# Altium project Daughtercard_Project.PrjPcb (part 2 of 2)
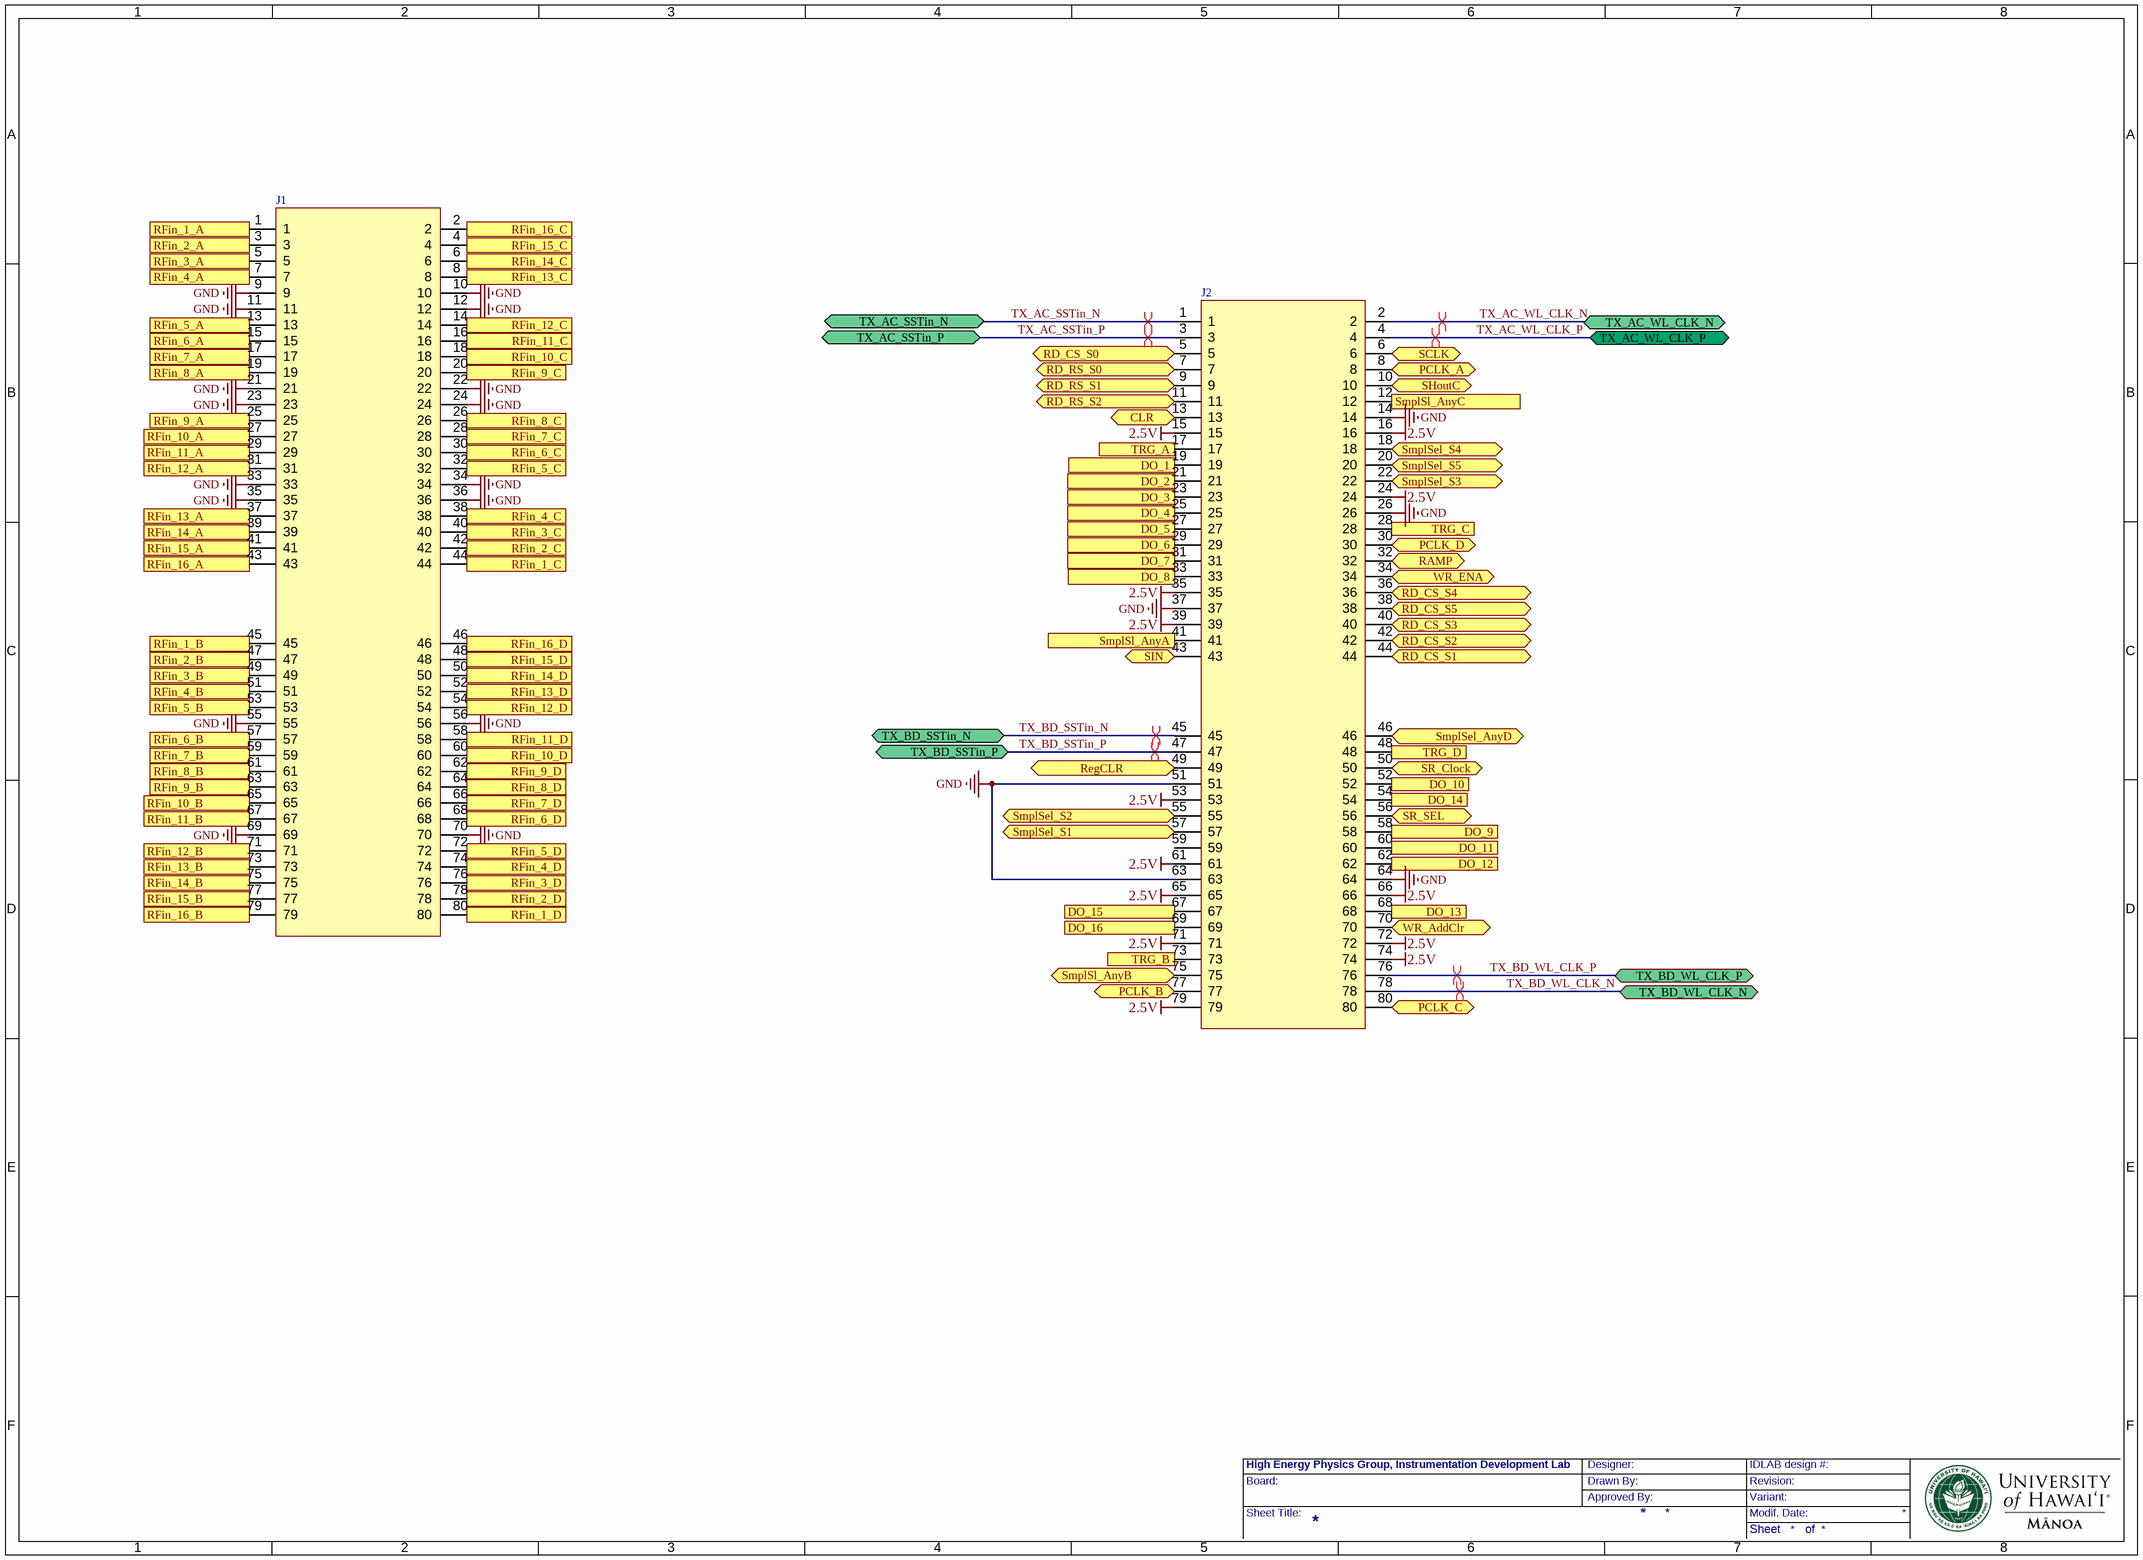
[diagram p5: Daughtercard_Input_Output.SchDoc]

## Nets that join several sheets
2.5V: TargetX_A (32 pins), TargetX_B (32 pins), TargetX_C (32 pins), TargetX_D (32 pins), Daughtercard_Input_Output (13 pins)
GND: TargetX_A (61 pins), TargetX_B (61 pins), TargetX_C (61 pins), TargetX_D (61 pins), Daughtercard_Input_Output (22 pins)
DO_1: TargetX_A (UA.91), TargetX_B (UB.91), TargetX_C (UC.91), TargetX_D (UD.91)
DO_2: TargetX_A (UA.90), TargetX_B (UB.90), TargetX_C (UC.90), TargetX_D (UD.90)
DO_3: TargetX_A (UA.89), TargetX_B (UB.89), TargetX_C (UC.89), TargetX_D (UD.89)
DO_4: TargetX_A (UA.88), TargetX_B (UB.88), TargetX_C (UC.88), TargetX_D (UD.88)
DO_5: TargetX_A (UA.87), TargetX_B (UB.87), TargetX_C (UC.87), TargetX_D (UD.87)
DO_6: TargetX_A (UA.86), TargetX_B (UB.86), TargetX_C (UC.86), TargetX_D (UD.86)
DO_7: TargetX_A (UA.85), TargetX_B (UB.85), TargetX_C (UC.85), TargetX_D (UD.85)
DO_8: TargetX_A (UA.84), TargetX_B (UB.84), TargetX_C (UC.84), TargetX_D (UD.84)
DO_9: TargetX_A (UA.76), TargetX_B (UB.76), TargetX_C (UC.76), TargetX_D (UD.76)
DO_10: TargetX_A (UA.75), TargetX_B (UB.75), TargetX_C (UC.75), TargetX_D (UD.75)
DO_11: TargetX_A (UA.74), TargetX_B (UB.74), TargetX_C (UC.74), TargetX_D (UD.74)
DO_12: TargetX_A (UA.73), TargetX_B (UB.73), TargetX_C (UC.73), TargetX_D (UD.73)
DO_13: TargetX_A (UA.72), TargetX_B (UB.72), TargetX_C (UC.72), TargetX_D (UD.72)
DO_14: TargetX_A (UA.71), TargetX_B (UB.71), TargetX_C (UC.71), TargetX_D (UD.71)
DO_15: TargetX_A (UA.70), TargetX_B (UB.70), TargetX_C (UC.70), TargetX_D (UD.70)
DO_16: TargetX_A (UA.69), TargetX_B (UB.69), TargetX_C (UC.69), TargetX_D (UD.69)
PCLK_A: TargetX_A (UA.37), Daughtercard_Input_Output (J2.8)
PCLK_B: TargetX_B (UB.37), Daughtercard_Input_Output (J2.77)
PCLK_C: TargetX_C (UC.37), Daughtercard_Input_Output (J2.80)
PCLK_D: TargetX_D (UD.37), Daughtercard_Input_Output (J2.30)
RD_CS_S0: TargetX_A (UA.46), TargetX_B (UB.46), TargetX_C (UC.46), TargetX_D (UD.46), Daughtercard_Input_Output (J2.5)
RD_CS_S1: TargetX_A (UA.47), TargetX_B (UB.47), TargetX_C (UC.47), TargetX_D (UD.47), Daughtercard_Input_Output (J2.44)
RD_CS_S2: TargetX_A (UA.48), TargetX_B (UB.48), TargetX_C (UC.48), TargetX_D (UD.48), Daughtercard_Input_Output (J2.42)
RD_CS_S3: TargetX_A (UA.49), TargetX_B (UB.49), TargetX_C (UC.49), TargetX_D (UD.49), Daughtercard_Input_Output (J2.40)
RD_CS_S4: TargetX_A (UA.50), TargetX_B (UB.50), TargetX_C (UC.50), TargetX_D (UD.50), Daughtercard_Input_Output (J2.36)
RD_CS_S5: TargetX_A (UA.51), TargetX_B (UB.51), TargetX_C (UC.51), TargetX_D (UD.51), Daughtercard_Input_Output (J2.38)
RD_RS_S0: TargetX_A (UA.105), TargetX_B (UB.105), TargetX_C (UC.105), TargetX_D (UD.105), Daughtercard_Input_Output (J2.7)
RD_RS_S1: TargetX_A (UA.104), TargetX_B (UB.104), TargetX_C (UC.104), TargetX_D (UD.104), Daughtercard_Input_Output (J2.9)
RD_RS_S2: TargetX_A (UA.103), TargetX_B (UB.103), TargetX_C (UC.103), TargetX_D (UD.103), Daughtercard_Input_Output (J2.11)
RegCLR: TargetX_A (UA.99), TargetX_B (UB.99), TargetX_C (UC.99), TargetX_D (UD.99), Daughtercard_Input_Output (J2.49)
RFin_1_A: TargetX_A (R1A.2 UA.1), Daughtercard_Input_Output (J1.1)
RFin_1_B: TargetX_B (R1B.2 UB.1), Daughtercard_Input_Output (J1.45)
RFin_1_C: TargetX_C (R1C.2 UC.1), Daughtercard_Input_Output (J1.44)
RFin_1_D: TargetX_D (R1D.2 UD.1), Daughtercard_Input_Output (J1.80)
RFin_2_A: TargetX_A (R2A.2 UA.3), Daughtercard_Input_Output (J1.3)
RFin_2_B: TargetX_B (R2B.2 UB.3), Daughtercard_Input_Output (J1.47)
RFin_2_C: TargetX_C (R2C.2 UC.3), Daughtercard_Input_Output (J1.42)
RFin_2_D: TargetX_D (R2D.2 UD.3), Daughtercard_Input_Output (J1.78)
RFin_3_A: TargetX_A (R3A.2 UA.5), Daughtercard_Input_Output (J1.5)
RFin_3_B: TargetX_B (R3B.2 UB.5), Daughtercard_Input_Output (J1.49)
RFin_3_C: TargetX_C (R3C.2 UC.5), Daughtercard_Input_Output (J1.40)
RFin_3_D: TargetX_D (R3D.2 UD.5), Daughtercard_Input_Output (J1.76)
RFin_4_A: TargetX_A (R4A.2 UA.7), Daughtercard_Input_Output (J1.7)
RFin_4_B: TargetX_B (R4B.2 UB.7), Daughtercard_Input_Output (J1.51)
RFin_4_C: TargetX_C (R4C.2 UC.7), Daughtercard_Input_Output (J1.38)
RFin_4_D: TargetX_D (R4D.2 UD.7), Daughtercard_Input_Output (J1.74)
RFin_5_A: TargetX_A (R5A.2 UA.9), Daughtercard_Input_Output (J1.13)
RFin_5_B: TargetX_B (R5B.2 UB.9), Daughtercard_Input_Output (J1.53)
RFin_5_C: TargetX_C (R5C.2 UC.9), Daughtercard_Input_Output (J1.32)
RFin_5_D: TargetX_D (R5D.2 UD.9), Daughtercard_Input_Output (J1.72)
RFin_6_A: TargetX_A (R6A.2 UA.11), Daughtercard_Input_Output (J1.15)
RFin_6_B: TargetX_B (R6B.2 UB.11), Daughtercard_Input_Output (J1.57)
RFin_6_C: TargetX_C (R6C.2 UC.11), Daughtercard_Input_Output (J1.30)
RFin_6_D: TargetX_D (R6D.2 UD.11), Daughtercard_Input_Output (J1.68)
RFin_7_A: TargetX_A (R7A.2 UA.13), Daughtercard_Input_Output (J1.17)
RFin_7_B: TargetX_B (R7B.2 UB.13), Daughtercard_Input_Output (J1.59)
RFin_7_C: TargetX_C (R7C.2 UC.13), Daughtercard_Input_Output (J1.28)
RFin_7_D: TargetX_D (R7D.2 UD.13), Daughtercard_Input_Output (J1.66)
RFin_8_A: TargetX_A (R8A.2 UA.15), Daughtercard_Input_Output (J1.19)
RFin_8_B: TargetX_B (R8B.2 UB.15), Daughtercard_Input_Output (J1.61)
RFin_8_C: TargetX_C (R8C.2 UC.15), Daughtercard_Input_Output (J1.26)
RFin_8_D: TargetX_D (R8D.2 UD.15), Daughtercard_Input_Output (J1.64)
RFin_9_A: TargetX_A (R9A.2 UA.17), Daughtercard_Input_Output (J1.25)
RFin_9_B: TargetX_B (R9B.2 UB.17), Daughtercard_Input_Output (J1.63)
RFin_9_C: TargetX_C (R9C.2 UC.17), Daughtercard_Input_Output (J1.20)
RFin_9_D: TargetX_D (R9D.2 UD.17), Daughtercard_Input_Output (J1.62)
RFin_10_A: TargetX_A (R10A.2 UA.19), Daughtercard_Input_Output (J1.27)
RFin_10_B: TargetX_B (R10B.2 UB.19), Daughtercard_Input_Output (J1.65)
RFin_10_C: TargetX_C (R10C.2 UC.19), Daughtercard_Input_Output (J1.18)
RFin_10_D: TargetX_D (R10D.2 UD.19), Daughtercard_Input_Output (J1.60)
RFin_11_A: TargetX_A (R11A.2 UA.21), Daughtercard_Input_Output (J1.29)
RFin_11_B: TargetX_B (R11B.2 UB.21), Daughtercard_Input_Output (J1.67)
RFin_11_C: TargetX_C (R11C.2 UC.21), Daughtercard_Input_Output (J1.16)
RFin_11_D: TargetX_D (R11D.2 UD.21), Daughtercard_Input_Output (J1.58)
RFin_12_A: TargetX_A (R12A.2 UA.23), Daughtercard_Input_Output (J1.31)
RFin_12_B: TargetX_B (R12B.2 UB.23), Daughtercard_Input_Output (J1.71)
RFin_12_C: TargetX_C (R12C.2 UC.23), Daughtercard_Input_Output (J1.14)
RFin_12_D: TargetX_D (R12D.2 UD.23), Daughtercard_Input_Output (J1.54)
RFin_13_A: TargetX_A (R13A.2 UA.25), Daughtercard_Input_Output (J1.37)
RFin_13_B: TargetX_B (R13B.2 UB.25), Daughtercard_Input_Output (J1.73)
RFin_13_C: TargetX_C (R13C.2 UC.25), Daughtercard_Input_Output (J1.8)
RFin_13_D: TargetX_D (R13D.2 UD.25), Daughtercard_Input_Output (J1.52)
RFin_14_A: TargetX_A (R14A.2 UA.27), Daughtercard_Input_Output (J1.39)
RFin_14_B: TargetX_B (R14B.2 UB.27), Daughtercard_Input_Output (J1.75)
RFin_14_C: TargetX_C (R14C.2 UC.27), Daughtercard_Input_Output (J1.6)
RFin_14_D: TargetX_D (R14D.2 UD.27), Daughtercard_Input_Output (J1.50)
RFin_15_A: TargetX_A (R15A.2 UA.29), Daughtercard_Input_Output (J1.41)
RFin_15_B: TargetX_B (R15B.2 UB.29), Daughtercard_Input_Output (J1.77)
RFin_15_C: TargetX_C (R15C.2 UC.29), Daughtercard_Input_Output (J1.4)
RFin_15_D: TargetX_D (R15D.2 UD.29), Daughtercard_Input_Output (J1.48)
RFin_16_A: TargetX_A (R16A.2 UA.31), Daughtercard_Input_Output (J1.43)
RFin_16_B: TargetX_B (R16B.2 UB.31), Daughtercard_Input_Output (J1.79)
RFin_16_C: TargetX_C (R16C.2 UC.31), Daughtercard_Input_Output (J1.2)
RFin_16_D: TargetX_D (R16D.2 UD.31), Daughtercard_Input_Output (J1.46)
SCLK: TargetX_A (UA.36), TargetX_B (UB.36), TargetX_C (UC.36), TargetX_D (UD.36), Daughtercard_Input_Output (J2.6)
SHoutC: TargetX_C (UC.38), Daughtercard_Input_Output (J2.10)
SIN: TargetX_A (UA.35), TargetX_B (UB.35), TargetX_C (UC.35), TargetX_D (UD.35), Daughtercard_Input_Output (J2.43)
SmplSel_AnyD: TargetX_D (UD.66), Daughtercard_Input_Output (J2.46)
SmplSel_S1: TargetX_A (UA.65), TargetX_B (UB.65), TargetX_C (UC.65), TargetX_D (UD.65), Daughtercard_Input_Output (J2.57)
SmplSel_S2: TargetX_A (UA.64), TargetX_B (UB.64), TargetX_C (UC.64), TargetX_D (UD.64), Daughtercard_Input_Output (J2.55)
SmplSel_S3: TargetX_A (UA.63), TargetX_B (UB.63), TargetX_C (UC.63), TargetX_D (UD.63), Daughtercard_Input_Output (J2.22)
SmplSel_S4: TargetX_A (UA.62), TargetX_B (UB.62), TargetX_C (UC.62), TargetX_D (UD.62), Daughtercard_Input_Output (J2.18)
SmplSel_S5: TargetX_A (UA.61), TargetX_B (UB.61), TargetX_C (UC.61), TargetX_D (UD.61), Daughtercard_Input_Output (J2.20)
SmplSl_AnyA: TargetX_A (UA.66), Daughtercard_Input_Output (J2.41)
SmplSl_AnyB: TargetX_B (UB.66), Daughtercard_Input_Output (J2.75)
SmplSl_AnyC: TargetX_C (UC.66), Daughtercard_Input_Output (J2.12)
SR_Clock: TargetX_A (UA.80), TargetX_B (UB.80), TargetX_C (UC.80), TargetX_D (UD.80), Daughtercard_Input_Output (J2.50)
SR_Sel: TargetX_A (UA.81), TargetX_B (UB.81), TargetX_C (UC.81), TargetX_D (UD.81), Daughtercard_Input_Output (J2.56)
TRG_A: TargetX_A (6 pins), Daughtercard_Input_Output (J2.17)
TRG_B: TargetX_B (6 pins), Daughtercard_Input_Output (J2.73)
TRG_C: TargetX_C (6 pins), Daughtercard_Input_Output (J2.28)
TRG_D: TargetX_D (6 pins), Daughtercard_Input_Output (J2.48)
TX_AC_SSTin_N: TargetX_A (UA.126), TargetX_C (RsstC.1 UC.126), Daughtercard_Input_Output (J2.1)
TX_AC_SSTin_P: TargetX_A (UA.125), TargetX_C (RsstC.2 UC.125), Daughtercard_Input_Output (J2.3)
TX_AC_WL_CLK_N: TargetX_A (RwA.1 UA.57), TargetX_C (UC.57), Daughtercard_Input_Output (J2.2)
TX_AC_WL_CLK_P: TargetX_A (RwA.2 UA.58), TargetX_C (UC.58), Daughtercard_Input_Output (J2.4)
TX_BD_SSTin_N: TargetX_B (UB.126), TargetX_D (RsstD.1 UD.126), Daughtercard_Input_Output (J2.45)
TX_BD_SSTin_P: TargetX_B (UB.125), TargetX_D (RsstD.2 UD.125), Daughtercard_Input_Output (J2.47)
TX_BD_WL_CLK_N: TargetX_B (RwB.1 UB.57), TargetX_D (UD.57), Daughtercard_Input_Output (J2.78)
TX_BD_WL_CLK_P: TargetX_B (RwB.2 UB.58), TargetX_D (UD.58), Daughtercard_Input_Output (J2.76)
Vped1: TargetX_A (18 pins), TargetX_B (18 pins), TargetX_C (18 pins), TargetX_D (18 pins)
WR_AddClr: TargetX_A (UA.54), TargetX_B (UB.54), TargetX_C (UC.54), TargetX_D (UD.54), Daughtercard_Input_Output (J2.70)
WR_ENA: TargetX_A (UA.55 UA.56), TargetX_B (UB.55 UB.56), TargetX_C (UC.55 UC.56), TargetX_D (UD.55 UD.56), Daughtercard_Input_Output (J2.34)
